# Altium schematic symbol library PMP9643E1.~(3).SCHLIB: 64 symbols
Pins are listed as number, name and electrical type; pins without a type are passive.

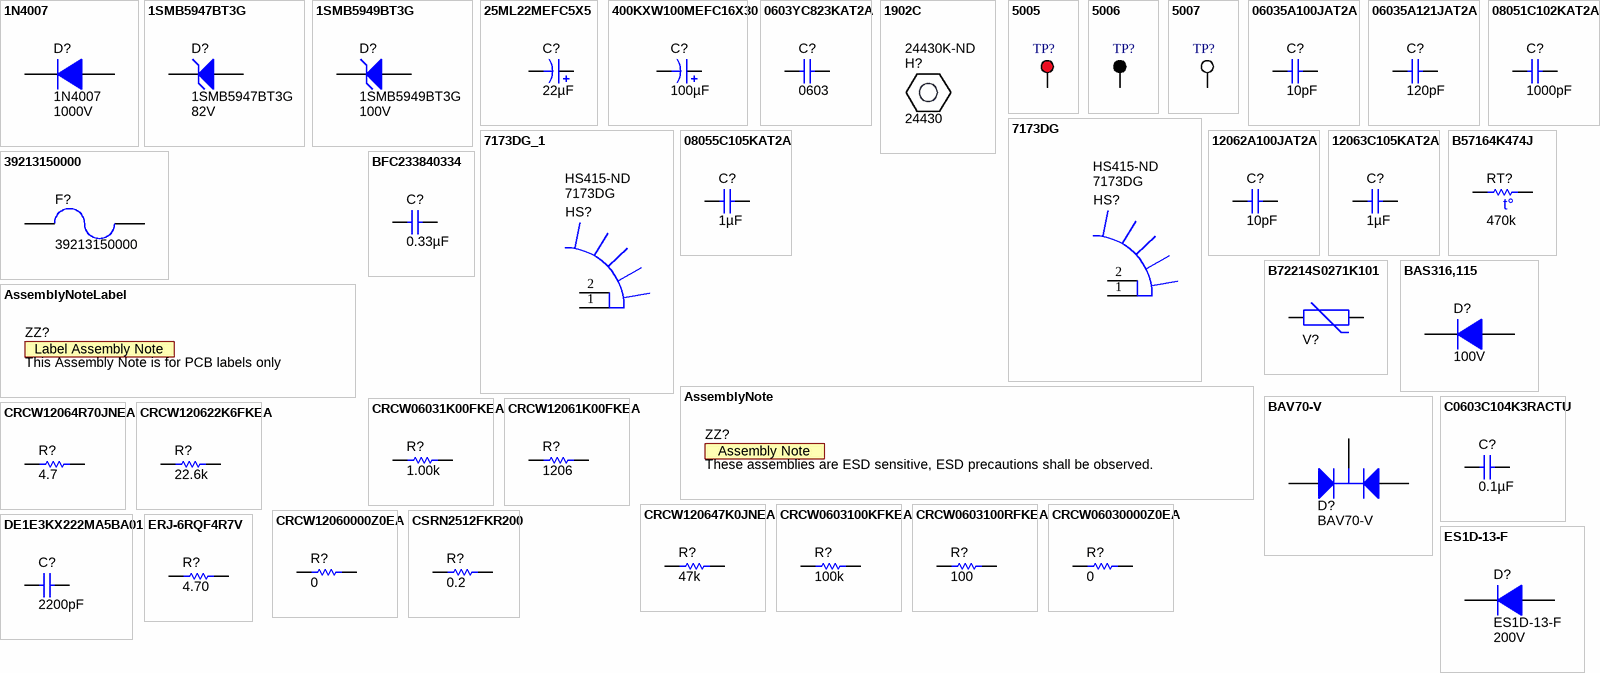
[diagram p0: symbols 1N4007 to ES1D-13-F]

## 1N4007
designator D?  value 1000V
Diode, P-N, 1000V, 1A, TH; Manufacturer: Fairchild Semiconductor; U/M: EA; Vf_V: 1.1; Value2: 1.1V; Io_A: 1; Vr_V: 1000; TJmax_C: 175; RJC_CperW: 50
signal-integrity model Diode
footprint DO-41
footprint DO-41_15mm
pins: 1 K, 2 A

## 1SMB5947BT3G
designator D?  value 82V
Diode, Zener, 82V, 550mW, SMB; Manufacturer: ON Semiconductor; U/M: EA; Power_W: 0.55; Vz_V: 82; Value1: 0.55W; RJA_CperW: 226
signal-integrity model Diode
footprint SMB
pins: 1 K, 2 A

## 1SMB5949BT3G
designator D?  value 100V
Diode, Zener, 100V, 550mW, SMB; Manufacturer: ON Semiconductor; U/M: EA; Power_W: 0.55; Vz_V: 100; Value1: 0.55W; RJA_CperW: 226
signal-integrity model Diode
footprint SMB
pins: 1 K, 2 A

## 25ML22MEFC5X5
designator C?  ValueDisplayed: 22µF  (hidden comment: 25ML22MEFC5X5)
CAP, AL, 22uF, 25V, +/-20%, TH; Manufacturer: Rubycon; Polarized: Y; CompType: Capacitor; U/M: EA; Cap_F: 0.000022; Tolerance_%: 20; Value1: Unknown; VDC_V: 25; IRMS_A: 0.042; TaMin_C: -40; TaMax_C: 105; Cap_Case: 5x5
signal-integrity model Cap
simulation model Cap
footprint ML_500x500
pins: 1 +, 2 -

## 400KXW100MEFC16X30
designator C?  ValueDisplayed: 100µF  (hidden comment: 400KXW100MEFC16X30)
CAP, AL, 100uF, 400V, +/-20%, TH; Manufacturer: Rubycon; Polarized: Y; CompType: Capacitor; U/M: EA; Cap_F: 0.0001; Tolerance_%: 20; Value1: Unknown; VDC_V: 400; IRMS_A: 0.58; TaMin_C: -25; TaMax_C: 105; Cap_Case: RCAP, 16x30mm
signal-integrity model Cap
simulation model Cap
footprint CAPPR750W80D1600H3000 (Capacitor, Electrolytic, Radial; Body 16 x 30 mm (Dia.xH typ); Pin Spacing 7.5 mm (typ))
pins: 1 +, 2 -

## 0603YC823KAT2A
designator C?  PackageReference: 0603  (hidden comment: 0603YC823KAT2A)
CAP, CERM, 0.082uF, 16V, +/-10%, X7R, 0603; Manufacturer: AVX; Polarized: N; CompType: Capacitor; ValueDisplayed: 0.082µF; U/M: EA; Cap_F: 0.000000082; Tolerance_%: 10; ESR_Ohm: 0.042; Value1: 0.042 ohm; VDC_V: 16; TaMin_C: -55; TaMax_C: 125
signal-integrity model Cap
simulation model Cap
footprint 0603
footprint 0603M
footprint 0603L
footprint 0603_HV
pins: 1, 2

## 1902C
designator H?, comment 24430  Supplier Part Number: 24430K-ND
HEX STANDOFF M3 ALUMINUM 5MM; Manufacturer: Keystone Electronics; Threaded/Unthreaded: Threaded; Gender: Female, Female; Thread/Screw/Hole Size: M3 Thread; Between Board Height: 0.197" (5.00mm); Plating: Iridite
footprint Keystone_24430 (Hex Standoff, 5 x 0.5 threaded, Aluminium)

## 5005
designator TP?  (value not drawn)
Test Point, Compact, Red, TH; Manufacturer: Keystone; CompType: Test Point Loop; U/M: EA
footprint Keystone5005
pins: 1

## 5006
designator TP?  (value not drawn)
Test Point, Compact, Black, TH; Manufacturer: Keystone; CompType: Test Point Loop; U/M: EA
footprint Keystone5006
pins: 1

## 5007
designator TP?  (value not drawn)
Test Point, Compact, White, TH; Manufacturer: Keystone; CompType: Test Point Loop; U/M: EA
footprint Keystone5007
pins: 1

## 06035A100JAT2A
designator C?  ValueDisplayed: 10pF  (hidden comment: 06035A100JAT2A)
CAP, CERM, 10pF, 50V, +/-5%, C0G/NP0, 0603; Manufacturer: AVX; Polarized: N; CompType: Capacitor; U/M: EA; Cap_F: 0.00000000001; Tolerance_%: 5; ESR_Ohm: 0.403; Value1: 0.403 ohm; VDC_V: 50; TaMin_C: -55; TaMax_C: 125; Cap_Case: 0603
signal-integrity model Cap
simulation model Cap
footprint 0603
footprint 0603M
footprint 0603L
footprint 0603_HV
pins: 1, 2

## 06035A121JAT2A
designator C?  ValueDisplayed: 120pF  (hidden comment: 06035A121JAT2A)
CAP, CERM, 120pF, 50V, +/-5%, C0G/NP0, 0603; Manufacturer: AVX; Polarized: N; CompType: Capacitor; U/M: EA; Cap_F: 0.00000000012; Tolerance_%: 5; ESR_Ohm: 0.109; Value1: 0.109 ohm; VDC_V: 50; TaMin_C: -55; TaMax_C: 125; Cap_Case: 0603
signal-integrity model Cap
simulation model Cap
footprint 0603
footprint 0603M
footprint 0603L
footprint 0603_HV
pins: 1, 2

## 7173DG
designator HS?  Supplier Part Number 1: HS415-ND
BOARD LEVEL HEATSINK .375" TO-220; Manufacturer: Aavid Thermalloy; Attachment Method: Bolt On and PC Pin; Material Finish: Tin; Thermal Resistance @ Natural: 25.8°C/W; Thermal Resistance @ Forced Air Flow: 10.0°C/W @ 200 LFM; Power Dissipation @ Temperature Rise: 1.5W @ 50°C; Shape: Rectangular
footprint HSINK_7173DG (Aavid)
pins: 1, 2

## 7173DG_1
designator HS?, comment 7173DG  Supplier Part Number 1: HS415-ND
BOARD LEVEL HEATSINK .375" TO-220; Manufacturer: Aavid Thermalloy; Attachment Method: Bolt On and PC Pin; Material Finish: Tin; Thermal Resistance @ Natural: 25.8°C/W; Thermal Resistance @ Forced Air Flow: 10.0°C/W @ 200 LFM; Power Dissipation @ Temperature Rise: 1.5W @ 50°C; Shape: Rectangular
footprint HSINK_7173DG (Aavid)
pins: 1, 2

## 08051C102KAT2A
designator C?  ValueDisplayed: 1000pF  (hidden comment: 08051C102KAT2A)
CAP, CERM, 1000pF, 100V, +/-10%, X7R, 0805; Manufacturer: AVX; Polarized: N; CompType: Capacitor; U/M: EA; Cap_F: 0.000000001; Tolerance_%: 10; ESR_Ohm: 0.29; Value1: 0.29 ohm; VDC_V: 100; TaMin_C: -55; TaMax_C: 125; Cap_Case: 0805
signal-integrity model Cap
simulation model Cap
footprint 0805_HV
footprint 0805
footprint 0805M
footprint 0805L
pins: 1, 2

## 08055C105KAT2A
designator C?  ValueDisplayed: 1µF  (hidden comment: 08055C105KAT2A)
CAP, CERM, 1uF, 50V, +/-10%, X7R, 0805; Manufacturer: AVX; Polarized: N; CompType: Capacitor; U/M: EA; Cap_F: 0.000001; Tolerance_%: 10; Value1: Unknown; VDC_V: 50; TaMin_C: -55; TaMax_C: 125; Cap_Case: 0805
signal-integrity model Cap
simulation model Cap
footprint 0805_HV
footprint 0805
footprint 0805M
footprint 0805L
pins: 1, 2

## 12062A100JAT2A
designator C?  ValueDisplayed: 10pF  (hidden comment: 12062A100JAT2A)
CAP, CERM, 10pF, 200V, +/-5%, C0G/NP0, 1206; Manufacturer: AVX; Polarized: N; CompType: Capacitor; U/M: EA; Cap_F: 0.00000000001; Tolerance_%: 5; Value1: Unknown; VDC_V: 200; TaMin_C: -55; TaMax_C: 125; Cap_Case: 1206
signal-integrity model Cap
simulation model Cap
footprint 1206
footprint 1206M
footprint 1206L
pins: 1, 2

## 12063C105KAT2A
designator C?  ValueDisplayed: 1µF  (hidden comment: 12063C105KAT2A)
CAP, CERM, 1uF, 25V, +/-10%, X7R, 1206; Manufacturer: AVX; Polarized: N; CompType: Capacitor; U/M: EA; Cap_F: 0.000001; Tolerance_%: 10; ESR_Ohm: 0.013; Value1: 0.013 ohm; VDC_V: 25; TaMin_C: -55; TaMax_C: 125; Cap_Case: 1206
signal-integrity model Cap
simulation model Cap
footprint 1206
footprint 1206M
footprint 1206L
pins: 1, 2

## 39213150000
designator F?
Fuse, 3.15A, 250V, TH; Manufacturer: Littelfuse; U/M: EA; OpeningTime_200%_max: 120; VDC_V: 250; Irating_A: 3.15; Vdrop: 0.08; Soldering_Wave_MaxTemp_C: 260; Soldering_Wave_MaxTime_s: 5
footprint FUSE_392
pins: 1, 2

## AssemblyNote
designator ZZ?, comment These assemblies are ESD sensitive, ESD precautions shall be observed.  (no BOM)
SymbolCreator: codlsc; CompType: AssemblyNote
footprint AssemblyNote

## AssemblyNoteLabel
designator ZZ?, comment This Assembly Note is for PCB labels only  (no BOM)
SymbolCreator: a0412235
footprint AssemblyNoteLabel

## B57164K474J
designator RT?  value 470k  (hidden comment: B57164K474J)
Thermistor NTC, 470k ohm, 5%, Disc, 5.5x5mm; Manufacturer: EPCOS Inc; Tolerance_%: 5; Power_W: 0.45; TaMin_C: -55; TaMax_C: 125; U/M: EA
footprint THERM_B57164K
pins: 1, 2

## B72214S0271K101
designator V?  (value not drawn)
Varistor, 430V, 4.5KA, TH; Manufacturer: EPCOS Inc; SymbolCreator: a0412235
footprint VAR_B72214S0271
pins: 1, 2

## BAS316,115
designator D?  value 100V  (hidden comment: BAS316,115)
Diode, Ultrafast, 100V, 0.25A, SOD-323; Manufacturer: NXP Semiconductor; U/M: EA; Vf_V: 1.4; Value2: 1.4V; Io_A: 0.25; Vr_V: 100; TJmax_C: 150
signal-integrity model Diode
footprint sod-323
pins: 1 K, 2 A

## BAV70-V
designator D?
Diode, Switching, 70V, 0.25A, SOT-23; Manufacturer: Vishay-Semiconductor; SymbolCreator: a0412235; U/M: EA; Vf_V: 1.25; Value2: 1.25V; Io_A: 0.25; Vr_V: 70; TJmax_C: 150; RJC_CperW: 430
footprint SOT-23
footprint SOT-23M
footprint SOT-23L
pins: 1 A, 2 K, 3 C
1 alternate drawing of the same symbol

## BFC233840334
designator C?  ValueDisplayed: 0.33µF  (hidden comment: BFC233840334)
CAP, Film, 0.33uF, 630V, +/-20%, TH; Manufacturer: Vishay-Bccomponents; Polarized: N; CompType: Capacitor; U/M: EA; Cap_F: 0.00000033; Tolerance_%: 20; Value1: Unknown; VDC_V: 630; TaMin_C: -55; TaMax_C: 105; Cap_Case: 17.5x16.5x10mm
signal-integrity model Cap
simulation model Cap
footprint CAPRR1500W80D1750T1000H1650
pins: 1, 2

## C0603C104K3RACTU
designator C?  ValueDisplayed: 0.1µF  (hidden comment: C0603C104K3RACTU)
CAP, CERM, 0.1uF, 25V, +/-10%, X7R, 0603; Manufacturer: Kemet; Polarized: N; CompType: Capacitor; U/M: EA; Cap_F: 0.0000001; Tolerance_%: 10; Value1: Unknown; VDC_V: 25; TaMin_C: -55; TaMax_C: 125; Cap_Case: 0603
signal-integrity model Cap
simulation model Cap
footprint 0603
footprint 0603M
footprint 0603L
footprint 0603_HV
pins: 1, 2

## CRCW06031K00FKEA
designator R?  value 1.00k  (hidden comment: CRCW06031K00FKEA)
RES, 1.00k ohm, 1%, 0.1W, 0603; Manufacturer: Vishay-Dale; CompType: Resistor; Res_ohm: 1000; Value_Code: 1k00; Tolerance_%: 1; Power_W: 0.1; VDC_V: 75; TempCo: 100 ppm/C; EIA_Code: E96; U/M: EA
signal-integrity model Resistor
simulation model Resistor
footprint 0603
footprint 0603M
footprint 0603L
footprint 0603_HV
pins: 1, 2

## CRCW12061K00FKEA
designator R?  PackageReference: 1206  (hidden comment: CRCW12061K00FKEA)
RES, 1.00k ohm, 1%, 0.25W, 1206; Manufacturer: Vishay-Dale; CompType: Resistor; Res_ohm: 1000; Value_Code: 1k00; Tolerance_%: 1; Power_W: 0.25; VDC_V: 200; TempCo: 100 ppm/C; EIA_Code: E96; U/M: EA
signal-integrity model Resistor
simulation model Resistor
footprint 1206
footprint 1206M
footprint 1206L
pins: 1, 2

## CRCW12064R70JNEA
designator R?  value 4.7  (hidden comment: CRCW12064R70JNEA)
RES, 4.7 ohm, 5%, 0.25W, 1206; Manufacturer: Vishay-Dale; CompType: Resistor; Value_Code: 4R70; Tolerance_%: 5; Power_W: 0.25; VDC_V: 200; TempCo: 200 ppm/C; EIA_Code: E24; U/M: EA
signal-integrity model Resistor
simulation model Resistor
footprint 1206
footprint 1206M
footprint 1206L
pins: 1, 2

## CRCW120622K6FKEA
designator R?  value 22.6k  (hidden comment: CRCW120622K6FKEA)
RES, 22.6k ohm, 1%, 0.25W, 1206; Manufacturer: Vishay-Dale; CompType: Resistor; Res_ohm: 22600; Value_Code: 22k6; Tolerance_%: 1; Power_W: 0.25; VDC_V: 200; TempCo: 100 ppm/C; EIA_Code: E96; U/M: EA
signal-integrity model Resistor
simulation model Resistor
footprint 1206
footprint 1206M
footprint 1206L
pins: 1, 2

## CRCW120647K0JNEA
designator R?, comment value 47k  (hidden comment: CRCW120647K0FKEA)
RES, 47k ohm, 5%, 0.25W, 1206; Manufacturer: Vishay Dale; Description: RES 47.0K OHM 1/4W 1% 1206 SMD; Tolerance_%: ±1%; Power_W: 0.25W, 1/4W; TempCo: ±100ppm/°C
signal-integrity model Resistor
simulation model Resistor
footprint 1206
footprint 1206M
footprint 1206L
pins: 1, 2

## CRCW0603100KFKEA
designator R?  value 100k  (hidden comment: CRCW0603100KFKEA)
RES, 100k ohm, 1%, 0.1W, 0603; Manufacturer: Vishay-Dale; CompType: Resistor; Res_ohm: 100000; Tolerance_%: 1; Power_W: 0.1; VDC_V: 75; TempCo: 100 ppm/C; EIA_Code: E96; U/M: EA
signal-integrity model Resistor
simulation model Resistor
footprint 0603
footprint 0603M
footprint 0603L
footprint 0603_HV
pins: 1, 2

## CRCW0603100RFKEA
designator R?  value 100  (hidden comment: CRCW0603100RFKEA)
RES, 100 ohm, 1%, 0.1W, 0603; Manufacturer: Vishay-Dale; CompType: Resistor; Value_Code: 100R; Tolerance_%: 1; Power_W: 0.1; VDC_V: 75; TempCo: 100 ppm/C; EIA_Code: E96; U/M: EA
signal-integrity model Resistor
simulation model Resistor
footprint 0603
footprint 0603M
footprint 0603L
footprint 0603_HV
pins: 1, 2

## CRCW06030000Z0EA
designator R?  value 0  (hidden comment: CRCW06030000Z0EA)
RES, 0 ohm, 5%, 0.1W, 0603; Manufacturer: Vishay-Dale; CompType: Resistor; Value_Code: 0000; Tolerance_%: 5; Power_W: 0.1; VDC_V: 75; TempCo: 200 ppm/C; EIA_Code: E24; U/M: EA
signal-integrity model Resistor
simulation model Resistor
footprint 0603
footprint 0603M
footprint 0603L
footprint 0603_HV
pins: 1, 2

## CRCW12060000Z0EA
designator R?  value 0  (hidden comment: CRCW12060000Z0EA)
RES, 0 ohm, 5%, 0.25W, 1206; Manufacturer: Vishay-Dale; CompType: Resistor; Value_Code: 0000; Tolerance_%: 5; Power_W: 0.25; VDC_V: 200; TempCo: 200 ppm/C; EIA_Code: E24; U/M: EA
signal-integrity model Resistor
simulation model Resistor
footprint 1206
footprint 1206M
footprint 1206L
pins: 1, 2

## CSRN2512FKR200
designator R?  value 0.2  (hidden comment: CSRN2512FKR200)
RES, 0.2 ohm, 1%, 2W, 2512; Manufacturer: Stackpole Electronics Inc; CompType: Resistor; Value_Code: R200; Tolerance_%: 1; Power_W: 2; TempCo: 200 ppm/C; EIA_Code: E96; U/M: EA
signal-integrity model Resistor
simulation model Resistor
footprint 2512M
footprint 2512L
footprint 2512
pins: 1, 2

## DE1E3KX222MA5BA01
designator C?  ValueDisplayed: 2200pF  (hidden comment: DE1E3KX222MA5BA01)
CAP, CERM, 2200pF, 250V, +/-20%, E, Disc 10x8mm; Manufacturer: MuRata; VDC_V: 250; Tolerance_%: 20; Polarized: N; CompType: Capacitor; U/M: EA; Cap_F: 0.0000000022; Value1: Unknown; TaMin_C: -25; TaMax_C: 85; Cap_Case: CAPRD1000W60D1000H1400
signal-integrity model Cap
simulation model Cap
footprint CAPRD1000W60D1000H1400
pins: 1, 2

## ERJ-6RQF4R7V
designator R?  value 4.70  (hidden comment: ERJ-6RQF4R7V)
RES, 4.70 ohm, 1%, 0.125W, 0805; Manufacturer: Panasonic; CompType: Resistor; TempCo: 200 ppm/C; Tolerance_%: 1; Power_W: 0.125; Res_ohm: 4.7; Value_Code: 4R70; U/M: EA
signal-integrity model Resistor
simulation model Resistor
footprint 0805_HV
footprint 0805
footprint 0805M
footprint 0805L
pins: 1, 2

## ES1D-13-F
designator D?  value 200V  (hidden comment: ES1D-13-F)
Diode, Ultrafast, 200V, 1A, SMA; Manufacturer: Diodes Inc.; U/M: EA; Vf_V: 0.92; Value2: 0.92V; Io_A: 1; Vr_V: 200; TJmax_C: 150; RJC_CperW: 25
signal-integrity model Diode
footprint SMA
pins: 1 K, 2 A

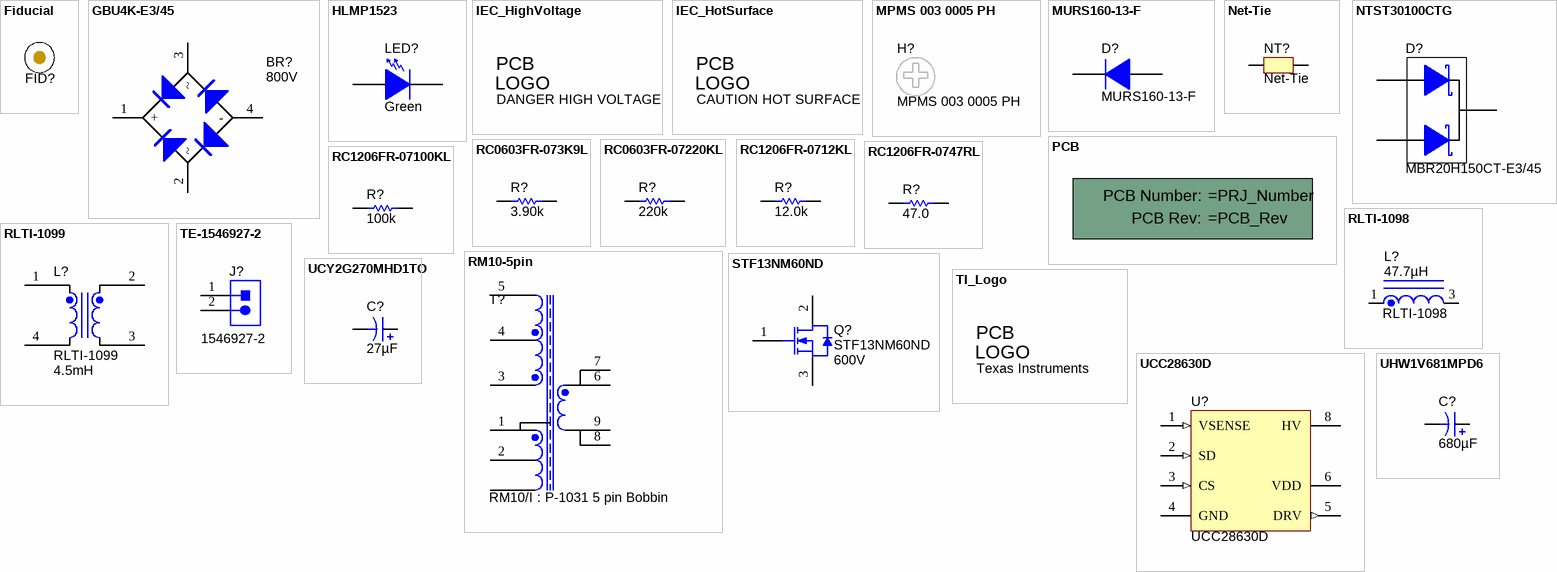
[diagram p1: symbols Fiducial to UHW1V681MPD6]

## Fiducial
designator FID?  (value not drawn)
Fiducial mark.  There is nothing to buy or mount.; SymbolCreator: codlsc
footprint Fiducial10-30
footprint Fiducial10-20
footprint Fiducial15-30
footprint Fiducial20-40
footprint Fiducial6.4-20
footprint Fiducial10-30_TopLayerKeepOutOnly
footprint Fiducial6.4-20_TopLayerKeepOutOnly
footprint Fiducial10-20_TopLayerKeepOutOnly
footprint Fiducial15-30_TopLayerKeepOutOnly
footprint Fiducial20-40_TopLayerKeepOutOnly

## GBU4K-E3/45
designator BR?  value 800V  (hidden comment: GBU4K-E3/45)
Diode, Switching-Bridge, 800V, 4A, TH; Manufacturer: Vishay-Semiconductor; U/M: EA; Vf_V: 1; Value2: 1V; Io_A: 4; Vr_V: 800; TJmax_C: 150; RJC_CperW: 4.2
footprint GBU
pins: 1 +, 2 ~, 3 ~, 4 -

## HLMP1523
designator LED?  value Green  (hidden comment: HLMP1523)
LED, Green, TH; Manufacturer: Everlight; Vf_V: 2.2; Value2: 2.2V; Io_A: 0.02; Tjmax_C: 100; Value1: W; U/M: EA
signal-integrity model Diode
footprint LED_HLMP1523
pins: 1 A, 2 K

## IEC_HighVoltage
designator Logo?, comment DANGER HIGH VOLTAGE  (no BOM)
IEC 61010-1 High Voltage Warning; SymbolCreator: codlsc
footprint IEC_HighVoltage_Large
footprint IEC_HighVoltage_Medium
footprint IEC_HighVoltage_Small

## IEC_HotSurface
designator Logo?, comment CAUTION HOT SURFACE  (no BOM)
IEC 61010-1 Hot Surface Warning; SymbolCreator: codlsc
footprint IEC_HotSurface_Large
footprint IEC_HotSurface_Medium
footprint IEC_HotSurface_Small

## MPMS 003 0005 PH
designator H?
MACHINE SCREW PAN PHILLIPS M3; Manufacturer: B&F Fastener Supply; CompType: Hardware
footprint BuildingFastener_MPMS_003_0005_PH

## MURS160-13-F
designator D?
Diode, Ultrafast, 600V, 1A, SMB; Manufacturer: Diodes Inc.; U/M: EA; Vf_V: 1.25; Value2: 1.25V; Io_A: 1; Vr_V: 600; TJmax_C: 150; RJC_CperW: 13
signal-integrity model Diode
simulation model DI_MURS160
footprint SMB
pins: 1 K, 2 A

## Net-Tie
designator NT?  (net tie, no BOM)
Single point connection between nets.; SymbolCreator: codlsc
footprint Net-Tie_10mil (10mil net tie, no solder mask opening, no solder paste)
footprint NetTie_1206 (1206 pads tied by 10mil copper trace which can be cut.  Part can be placed on pads.)
footprint Net-Tie_0805_HV
footprint NetTie_1206_NoOverlay (1206 pads tied by 10mil copper trace which can be cut.  Part can be placed on pads.)
footprint Net-Tie_0805_HV_NoOverlay (0805_HV pads tied by 10mil copper trace which can be cut.  An 0805 part can be placed on pads.)
footprint Net-Tie_10milWide_30milLong
footprint Net-Tie_20milWide_60milLong
pins: 1, 2

## NTST30100CTG
designator D?, comment MBR20H150CT-E3/45
Manufacturer: Vishay Semiconductor Diodes Division; Vr_V: 150V; Speed: Fast Recovery =< 500ns, > 200mA (Io); Type: Schottky; Value: 900mV @ 10A; Description: DIODE SCHOTTKY 150V 10A TO220AB; Diode Configuration: 1 Pair Common Cathode; Current - Reverse Leakage @ Vr: 5µA @ 150V; Current - Average Rectified (Io) (per Diode): 10A
signal-integrity model Diode
footprint TO-220AB_100mil (High Voltage staggered pins)
footprint TO-220AB_HORIZONTAL
footprint TO-220AB_HORIZONTAL_SMT
pins: 1 A, 2 K, 3 A

## PCB
designator !PCB?, comment Printed Circuit Board  (value not drawn)  (mechanical)
Manufacturer: Any; SymbolCreator: a0412235; CompType: PCB
1 alternate drawing of the same symbol

## RC0603FR-073K9L
designator R?  value 3.90k  (hidden comment: RC0603FR-073K9L)
RES, 3.90k ohm, 1%, 0.1W, 0603; Manufacturer: Yageo America; CompType: Resistor; Res_ohm: 3900; Value_Code: 3k90; Tolerance_%: 1; Power_W: 0.1; VDC_V: 150; TempCo: 200 ppm/C; U/M: EA
signal-integrity model Resistor
simulation model Resistor
footprint 0603
footprint 0603M
footprint 0603L
footprint 0603_HV
pins: 1, 2

## RC0603FR-07220KL
designator R?  value 220k  (hidden comment: RC0603FR-07220KL)
RES, 220k ohm, 1%, 0.1W, 0603; Manufacturer: Yageo America; TempCo: 200 ppm/C; Power_W: 0.1; Tolerance_%: 1; CompType: Resistor; Res_ohm: 220000; VDC_V: 150; U/M: EA
signal-integrity model Resistor
simulation model Resistor
footprint 0603
footprint 0603M
footprint 0603L
footprint 0603_HV
pins: 1, 2

## RC1206FR-0712KL
designator R?  value 12.0k  (hidden comment: RC1206FR-0712KL)
RES, 12.0k ohm, 1%, 0.25W, 1206; Manufacturer: Yageo America; CompType: Resistor; Res_ohm: 12000; Value_Code: 12k0; Tolerance_%: 1; Power_W: 0.25; VDC_V: 200; TempCo: 100 ppm/C; U/M: EA
signal-integrity model Resistor
simulation model Resistor
footprint 1206
footprint 1206M
footprint 1206L
pins: 1, 2

## RC1206FR-0747RL
designator R?  value 47.0  (hidden comment: RC1206FR-0747RL)
RES, 47.0 ohm, 1%, 0.25W, 1206; Manufacturer: Yageo America; CompType: Resistor; Res_ohm: 47; Value_Code: 47R0; Tolerance_%: 1; Power_W: 0.25; VDC_V: 200; TempCo: 100 ppm/C; U/M: EA
signal-integrity model Resistor
simulation model Resistor
footprint 1206
footprint 1206M
footprint 1206L
pins: 1, 2

## RC1206FR-07100KL
designator R?  value 100k  (hidden comment: RC1206FR-07100KL)
RES, 100k ohm, 1%, 0.25W, 1206; Manufacturer: Yageo America; CompType: Resistor; Res_ohm: 100000; Tolerance_%: 1; Power_W: 0.25; VDC_V: 200; TempCo: 100 ppm/C; EIA_Code: E96; U/M: EA
signal-integrity model Resistor
simulation model Resistor
footprint 1206
footprint 1206M
footprint 1206L
pins: 1, 2

## RLTI-1098
designator L?  ValueDisplayed: 47.7µH
Inductor, Toroid, ?, 47.7uH, A, 0.04 ohm, TH; Manufacturer: Renco Electronics; SymbolCreator: x0208326; Ind_H: 47.7E-6; Irms: 25A @ C rise; DCR_ohm: 0.04; U/M: EA
footprint RLTI-1098
pins: 1, 3

## RLTI-1099
designator L?  ValueDisplayed: 4.5mH
Inductor, Toroid, ?, 4.5mH, A, 0.05 ohm, TH; Manufacturer: Renco Electronics; SymbolCreator: a0799628; Ind_H: 4.5E-3; Irms: 25A @ C rise; DCR_ohm: 0.05; U/M: EA
footprint RLTI-1099
pins: 1, 2, 3, 4

## RM10-5pin
designator T?, comment RM10/I : P-1031 5 pin Bobbin
RM10-5pin
footprint RM10-5pin (Billy)
pins: 1, 2, 3, 4, 5, 6, 7, 8, 9

## STF13NM60ND
designator Q?  value 600V
MOSFET, N-CH, 600V, 11A, TO-220 FullPAK; Manufacturer: ST Microelectronics; Alternate Manufacturer: None; U/M: EA; ChType: N; VdsMax_V: 600; Value1: ? ohm; Value2: 24.5 nC; QgTyp_nC: 24.5; Vgs_V: 25; IdsMax_A: 11
footprint TO-220_FullPAK_Offset
pins: 1 G, 2 D, 3 S
1 alternate drawing of the same symbol

## TE-1546927-2
designator J?, comment 1546927-2
Manufacturer: TE Connectivity; Pitch: 0.325" (8.26mm); Number of Wire Entries: 2; Bottom Termination: PC Pin; Top Termination: Screws with Captive Plate; VDC_V: 300V; Material - Insulation: Polybutylene Terephthalate (PBT); Current Rating: 15A; Wire Gauge: 14-22 AWG; Material Flammability Rating: UL94 V-0; Barrier Type: 3 Wall (Tri); Description: CONN BARRIER BLOCK 2CIRC 8.26MM
footprint TE-1546927-2
pins: 1, 2
1 alternate drawing of the same symbol

## TI_Logo
designator Logo?, comment Texas Instruments  (no BOM)
Texas Instrument Corporate Signature; SymbolCreator: codlsc
footprint TI_Stacked_SolderMask_Medium
footprint TI_Stacked_SolderMask_Small
footprint TI_Stacked_Overlay_Medium
footprint TI_Stacked_Overlay_Small
footprint TI_Horizontal_SolderMask_Medium
footprint TI_Horizontal_SolderMask_Small
footprint TI_Horizontal_Overlay_Medium
footprint TI_Horizontal_Overlay_Small
footprint TI_Symbol_SolderMask_Small
footprint TI_Symbol_Overlay_Medium
footprint TI_Symbol_Overlay_Small
footprint TI_Symbol_SolderMask_Medium

## UCC28630D
designator U?
Green-Mode Flyback Controller, D0007A; Alternate Manufacturer: None; Manufacturer: Texas Instruments; SymbolCreator: a0411947; CompType: IC; U/M: EA
footprint D0007A_N
footprint D0007A_M
footprint D0007A_L
pins: 1 VSENSE (in), 2 SD (in), 3 CS (in), 4 GND (power), 5 DRV (out), 6 VDD (power), 8 HV (power)

## UCY2G270MHD1TO
designator C?  ValueDisplayed: 27µF  (hidden comment: UCY2G270MHD1TO)
CAP, AL, 27uF, 400V, +/-20%, TH; Manufacturer: Nichicon; Tolerance_%: 20; VDC_V: 400; Polarized: Y; CompType: Capacitor; U/M: EA; Cap_F: 0.000027; Value1: Unknown; IRMS_A: 0.36; TaMin_C: -40; TaMax_C: 105; Cap_Case: 12.5x20
signal-integrity model Cap
simulation model Cap
footprint CY_1250x2000
footprint CY_1250x2000_HorizontalUp
footprint CY_1250x2000_HorizontalDown
pins: 1 +, 2 -

## UHW1V681MPD6
designator C?  ValueDisplayed: 680µF  (hidden comment: UHW1V681MPD6)
CAP, AL, 680uF, 35V, +/-20%, 0.019 ohm, TH; Manufacturer: Nichicon; Polarized: Y; CompType: Capacitor; U/M: EA; Cap_F: 0.00068; Tolerance_%: 20; VDC_V: 35; ESR_Ohm: 0.019; IRMS_A: 2.5; TaMin_C: -40; TaMax_C: 105; Cap_Case: 10x20
signal-integrity model Cap
simulation model Cap
footprint HW_10x20
pins: 1 +, 2 -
